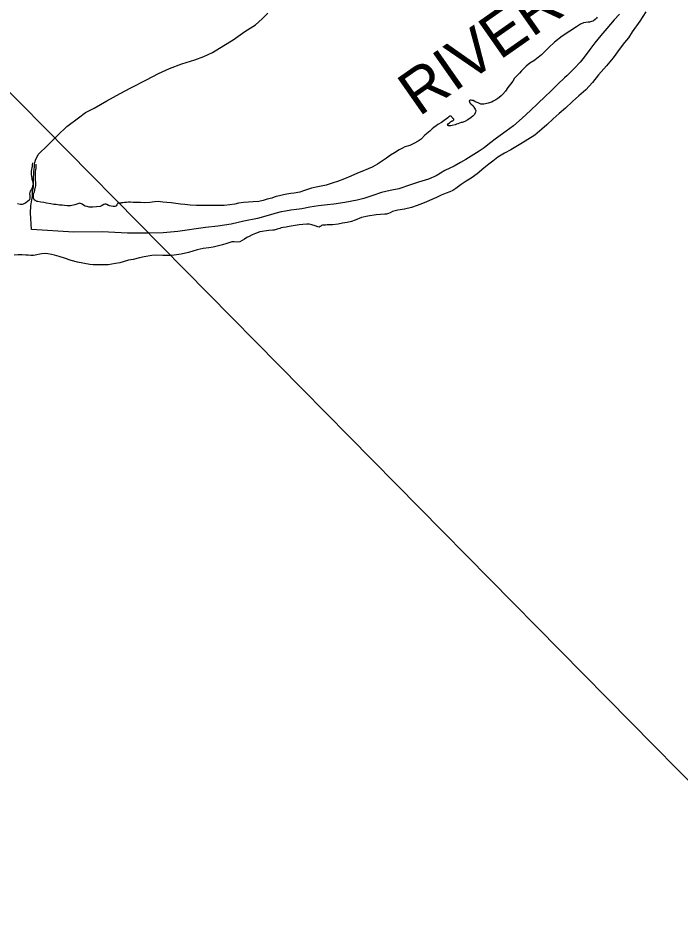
# Model space of a CAD drawing. Extents: x 31699 to 244310, y -8841 to 11474.
# Drawn here: x 101474 to 102106, y 1093 to 1951 of the extents above; entities that cross this region are included whole.
import ezdxf

# ---------------------------------------------------------------- set-up
doc = ezdxf.new("R2010")
doc.units = 0
for name, color, linetype in [('Level 48', 7, 'Continuous'), ('R_Draft', 7, 'Continuous'), ('R_Logo', 7, 'Continuous')]:
    doc.layers.add(name, color=color, linetype=linetype)

msp = doc.modelspace()

# ---------------------------------------------------------------- linework, layer by layer
at = {"layer": 'Level 48'}
msp.add_line((100000.09, 3366.76), (102655.5, 673.93), dxfattribs=at)
at = {"layer": 'R_Draft'}
for points in [[(102073.48, 1957.14), (102067.72, 1948.24)], [(102067.72, 1948.24), (102060.52, 1938.03), (102057, 1932.59), (102053.33, 1927.96), (102049.14, 1922.5), (102042.39, 1913.44), (102036, 1905.66), (102028.5, 1897.18), (102022.5, 1889.68), (102016.15, 1882.83), (102009.45, 1876.98), (102003.66, 1871.48), (101996.7, 1865.16), (101990.71, 1860.19), (101985.11, 1855.03), (101979, 1849.26), (101974.19, 1845.06), (101967.47, 1839.54), (101960.72, 1835.29), (101954.04, 1831.03), (101944.53, 1825.57), (101938.49, 1822.14), (101932.2, 1818.37), (101927.37, 1814.7), (101923.52, 1811.66), (101918.69, 1807.92), (101912.37, 1802.68), (101906.62, 1798.39), (101902.1, 1795.46), (101897.25, 1792.33), (101894.51, 1790.32), (101892.09, 1788.52), (101889.15, 1786.57), (101886.32, 1785.23), (101882.76, 1783.93), (101878.21, 1782.01), (101873.74, 1779.95), (101869.06, 1777.96), (101864.06, 1775.75), (101860.3, 1774.12), (101855.09, 1772.18), (101849.62, 1770.36), (101843.06, 1768.92), (101836.63, 1767.81), (101831.54, 1766.4), (101829.37, 1765.41), (101827.86, 1764.5), (101826.01, 1764.05), (101824.21, 1763.87), (101815.91, 1763.25), (101807.88, 1762.17), (101802.06, 1760.68), (101795.93, 1758.24), (101792.56, 1757.08), (101788.39, 1756.1), (101783.95, 1755.25), (101779.84, 1754.54), (101774.2, 1753.86), (101771.27, 1753.71), (101769.14, 1753.65), (101767.61, 1753.61), (101765.75, 1753.43), (101764.62, 1753.33), (101763.9, 1753.05), (101763.17, 1752.69), (101762.46, 1752.07), (101761.4, 1751.64), (101760.2, 1751.81), (101757.64, 1752.81), (101754.69, 1753.73), (101752.01, 1754.33), (101749.68, 1754.4), (101745.82, 1754.1), (101742.51, 1753.68), (101738.66, 1753.11), (101732.89, 1752.15), (101731.37, 1751.78), (101730.11, 1751.61), (101727.25, 1751.26), (101725.13, 1750.87), (101724.08, 1750.38), (101722.83, 1749.94), (101721.51, 1749.51), (101719.65, 1749.06), (101718.46, 1748.76), (101717.33, 1748.8)], [(102027.19, 1952.16), (102026.35, 1951.2), (102025.05, 1950.03), (102023.42, 1948.79), (102022.89, 1948.44), (102021.71, 1948.01), (102019.72, 1947.55), (102018.4, 1947.32), (102016.2, 1947.06), (102014.08, 1946.94), (102011.05, 1945.65), (102007.45, 1943.02), (102001.04, 1938.78), (101993.57, 1933.9), (101986.47, 1928.17), (101981, 1923.28), (101977.88, 1920.2), (101973.86, 1916.35), (101970.66, 1913.73), (101966.42, 1910.54), (101962.81, 1908.31), (101959.23, 1905.41), (101957.09, 1903.15), (101954.81, 1900.95), (101952.74, 1898.7), (101948.21, 1893.83), (101946.48, 1891.18), (101944.36, 1888.19), (101941.85, 1884.92), (101939.41, 1881.45), (101937.02, 1878.71), (101935.33, 1877), (101933.44, 1875.35), (101932.13, 1874.44), (101930.23, 1873.26), (101927.87, 1871.86), (101926.36, 1871.15), (101922.99, 1870.19), (101920.54, 1869.53), (101918.75, 1869.08), (101917.03, 1868.97), (101915.95, 1869.2), (101914.81, 1869.71), (101913.33, 1870.4), (101911.51, 1871.02), (101910.17, 1871.52), (101908.54, 1872.48), (101907.81, 1872.66), (101906.87, 1872.83), (101906.27, 1872.82), (101905.74, 1872.8)], [(101905.74, 1872.8), (101905.14, 1872.72), (101904.82, 1872.38), (101904.69, 1872.17), (101905.04, 1871.32), (101905.54, 1870.26), (101906.5, 1869.29), (101908.55, 1867.34), (101909.3, 1866.29), (101910.06, 1865.38), (101910.69, 1864.39), (101911.2, 1862.6), (101910.9, 1861.33), (101910.65, 1860.65), (101909.75, 1859.36), (101908.27, 1857.58), (101906.64, 1856.27), (101903.69, 1854.26), (101900.54, 1852.5), (101897.97, 1851.57), (101897.17, 1851.41), (101893.94, 1850.32), (101892.69, 1849.82), (101891.44, 1849.32), (101888.65, 1848.71), (101887.27, 1848.28), (101886.34, 1848.25), (101885.67, 1848.37), (101885.07, 1848.42), (101884.53, 1848.67), (101884.17, 1849.46), (101884.37, 1849.73), (101885.21, 1850.62), (101885.99, 1851.31), (101887.04, 1852.07), (101888.08, 1852.84), (101888.67, 1853.05), (101889.27, 1853.2), (101889.99, 1853.76), (101890.24, 1854.23), (101890.16, 1854.76), (101889.35, 1855.41), (101888.87, 1855.93), (101888.24, 1856.78), (101887.83, 1857.24), (101887.29, 1857.62), (101886.42, 1857.73), (101885.31, 1856.9), (101884.41, 1855.88), (101883.3, 1854.98), (101881.01, 1853.38), (101878.39, 1851.71), (101875.04, 1849.68), (101873.15, 1848.37), (101870.93, 1846.64), (101869.49, 1845.6), (101867.09, 1843.26), (101862.59, 1839.47), (101858.83, 1835.76), (101856.15, 1833.76), (101852.08, 1831.45), (101848.2, 1829.74), (101843.51, 1828.21), (101841.01, 1827.01), (101838.06, 1825.4), (101833.46, 1822.74), (101829.6, 1820.36), (101825.87, 1817.59), (101820.18, 1813.7), (101817.1, 1811.68), (101814.87, 1810.42), (101812.18, 1809.01), (101808.36, 1807.44), (101802.24, 1804.74), (101798.28, 1803.1), (101791.63, 1800.39), (101785.77, 1797.69), (101779.18, 1795.05), (101774.89, 1793.8), (101768.21, 1791.82), (101760.26, 1790.2), (101754.11, 1788.83), (101750.48, 1787.6), (101746.65, 1786.23), (101742.95, 1785.13), (101737.71, 1784.12), (101734.53, 1783.77), (101730.68, 1783.07), (101727.5, 1782.45), (101723.6, 1781.61), (101720.49, 1780.86), (101718.7, 1780.34), (101716.2, 1779.41)], [(101487.73, 1812.99), (101487.46, 1811.11), (101487.32, 1809.31), (101487.16, 1808.17), (101486.93, 1807.02), (101486.47, 1804.8), (101486.45, 1803.53), (101486.43, 1801.93), (101486.62, 1800.33), (101486.71, 1799.6), (101486.95, 1798.34), (101487.12, 1797.41), (101487.7, 1795.83), (101488.29, 1792.24), (101487.87, 1790.82), (101487.53, 1789.08), (101486.72, 1787.58), (101485.44, 1785.87), (101484.79, 1783.57), (101485.05, 1781.71), (101485.29, 1780.58), (101485.24, 1779.85), (101484.78, 1777.69), (101484.21, 1777.01), (101483.11, 1775.97), (101481.41, 1774.91), (101480.44, 1774.2), (101477.73, 1773.38), (101476.4, 1773.2), (101473.39, 1773.76)], [(101490.54, 1800.8), (101490.62, 1802.27), (101490.57, 1803.74), (101490.54, 1804.61), (101490.95, 1806.36), (101491.17, 1807.84), (101491.25, 1809.18), (101491.16, 1809.91), (101491.19, 1811.11), (101491.3, 1811.85)], [(101716.2, 1779.41), (101711.87, 1778.32), (101708.17, 1777.19), (101704.01, 1776.24), (101698.35, 1775.85), (101693.9, 1775.56), (101689.19, 1775.07), (101684.54, 1774.44), (101681.04, 1773.65), (101676.33, 1772.89), (101670.88, 1772.43), (101664.49, 1772.41), (101657.69, 1772.31), (101654.09, 1772.32), (101650.63, 1772.13), (101647.1, 1772.14), (101644.23, 1772.31), (101638.42, 1772.65), (101633.21, 1773.2), (101628.99, 1773.59), (101624.64, 1774.17), (101620.22, 1774.82), (101616.08, 1775.21), (101612.34, 1775.48), (101607.72, 1775.99), (101604.13, 1775.74), (101599.75, 1775.18), (101594.7, 1774.94), (101590.89, 1775.08), (101587.23, 1775.15), (101583.83, 1775.17), (101581.22, 1775.35), (101579.36, 1775.35), (101577.63, 1775.22), (101575.63, 1775.02), (101574.11, 1774.83), (101572.85, 1774.72), (101572.12, 1774.63), (101570.85, 1774.65), (101570.25, 1774.7), (101569.33, 1774.33), (101568.75, 1773.71), (101568.25, 1772.76), (101567.74, 1772.01), (101567.35, 1771.73), (101566.36, 1771.29), (101564.83, 1771.24), (101563.03, 1771.51), (101561.34, 1771.99), (101560.46, 1772.43), (101558.84, 1773.17), (101558.03, 1773.41), (101557.29, 1773.58), (101556.69, 1773.5), (101555.91, 1773.14), (101554.14, 1772.14), (101552.43, 1771.48), (101548.85, 1770.96), (101545.26, 1770.7), (101541.99, 1770.72), (101539.98, 1771.18), (101538.03, 1771.72), (101536.6, 1772.47), (101535.1, 1773.55), (101533.01, 1774.35), (101531.09, 1774.02), (101528.19, 1772.85), (101523.89, 1771.96), (101520.69, 1772.05), (101518.42, 1772.24), (101516.08, 1772.5), (101513.61, 1772.68), (101510.33, 1773.1), (101507.99, 1773.22), (101505.24, 1773.79), (101501.01, 1774.65), (101498.59, 1775.3), (101495.65, 1775.53), (101492.9, 1775.97), (101491.96, 1776.21), (101491.42, 1776.39), (101490.27, 1777.02), (101489.44, 1777.79), (101488.95, 1778.64), (101488.71, 1779.7), (101488.67, 1780.9), (101488.7, 1782.24), (101488.79, 1783.51), (101489.53, 1785.2), (101489.94, 1786.89), (101490.09, 1788.3), (101490.45, 1789.58), (101490.86, 1791.26), (101490.88, 1792.6), (101490.91, 1793.73), (101490.8, 1794.8), (101490.62, 1796.2), (101490.52, 1797.26), (101490.6, 1798.8), (101490.57, 1799.67), (101490.54, 1800.8)], [(101717.33, 1748.8), (101713.61, 1748.39), (101704.92, 1747.09), (101700.84, 1745.61), (101697.62, 1744.23), (101694.67, 1742.79), (101692.58, 1741.59), (101690.36, 1740.17), (101688.14, 1738.9), (101685.78, 1737.61), (101683.12, 1737.39), (101680.38, 1737.63), (101678.12, 1737.68), (101673.5, 1736.12), (101669.29, 1734.64), (101660.36, 1732.53), (101656.19, 1731.71), (101650.88, 1731.2), (101644.86, 1729.92), (101636.82, 1727.24), (101629.67, 1725.79), (101620.79, 1724.41), (101612.25, 1724.59), (101606.38, 1724.79), (101601.79, 1724.49), (101594.3, 1723.37), (101589.81, 1722.21), (101583.79, 1720.8), (101579.35, 1720.18), (101574.41, 1718.41), (101571.17, 1717.63), (101567.13, 1716.82), (101563.48, 1716.36), (101559.91, 1715.7), (101555.18, 1715.47), (101551.05, 1715.53), (101545.72, 1715.54), (101542.51, 1715.9), (101530.56, 1718.29), (101524.58, 1719.82), (101518.18, 1721.87), (101513.07, 1723.43), (101508.89, 1724.69), (101505.93, 1725.53), (101502.51, 1726.21), (101500.1, 1726.39), (101496.78, 1726.14), (101494.79, 1725.88), (101491.75, 1725.04), (101488.57, 1724.66), (101486.1, 1724.57), (101483.57, 1724.69), (101481.43, 1724.81), (101477.76, 1725.02), (101474.03, 1725.03), (101470.17, 1724.83)]]:
    msp.add_lwpolyline(points, dxfattribs=at)
at = {"layer": 'R_Logo'}
for points in [[(101717.13, 1763.95), (101702.63, 1759.83), (101689.59, 1757.25), (101677.55, 1754.43), (101664.76, 1752.38), (101652.93, 1751.37), (101626.48, 1747.45), (101612.46, 1746.17), (101599.94, 1745.87), (101578.61, 1746), (101554.18, 1747.23), (101527.27, 1746.83), (101486.74, 1749.38), (101485.73, 1765.3), (101486.24, 1772.07), (101487.18, 1777.78), (101487.68, 1780.87), (101487.72, 1783.54), (101487.78, 1785.68), (101488.29, 1788.23), (101488.75, 1790.45), (101488.72, 1791.52), (101488.79, 1793.39), (101488.71, 1795.66), (101488.74, 1796.8), (101488.79, 1799.14), (101488.96, 1802.08), (101489.15, 1804.49), (101489.26, 1806.9), (101489.53, 1808.85), (101489.72, 1811.06), (101489.75, 1812.13), (101489.92, 1813.2), (101490.63, 1815.7), (101492.99, 1821.06), (101502.35, 1829.93), (101511.83, 1839.34), (101520.61, 1847.79), (101531.52, 1856.18), (101538.42, 1861.03), (101546.48, 1865.25), (101558.64, 1872.21), (101571.32, 1879.33), (101581.67, 1884.76), (101596.54, 1892.42), (101608.07, 1898.23), (101618.43, 1903.27), (101630.21, 1907.75), (101642.94, 1911.59), (101651.3, 1914.69), (101659.51, 1918.31), (101670.54, 1924.97), (101679.35, 1930.62), (101690.55, 1938.35), (101700.6, 1944.84), (101707.14, 1950.48), (101712.44, 1956.16)], [(102048.43, 1955.06), (102043.44, 1949.52), (102036.26, 1941.52), (102030.64, 1934.83), (102024.7, 1927.59), (102020.01, 1921.39), (102014.67, 1913.9), (102010.86, 1909.33), (102005.36, 1903.44), (101998.48, 1896.58), (101995.88, 1894.11), (101989.5, 1888.33), (101982.75, 1881.61), (101977.43, 1876.32), (101970.55, 1869.66), (101963.33, 1862.93), (101955.53, 1855.71), (101947.26, 1848.34), (101940.14, 1843.15), (101930.93, 1836.49), (101924.33, 1831.44), (101919.11, 1827.36), (101914.47, 1824.17), (101906.87, 1819.29), (101901.56, 1816.08), (101896.44, 1813.2), (101890.47, 1809.91), (101881.59, 1805.6), (101873.19, 1800.7), (101865.96, 1797.37), (101856.44, 1794.64), (101848.65, 1792.03), (101837.56, 1788.13), (101829.48, 1786.51)], [(101829.48, 1786.51), (101820.94, 1784.68), (101811.9, 1781.63), (101804.17, 1779.09), (101797.69, 1777.32), (101786.16, 1775.21), (101775.48, 1773.58), (101769.37, 1772.82), (101760.94, 1771.93), (101752.52, 1770.7), (101745.03, 1769.23), (101739.99, 1768.3), (101734.42, 1767.68), (101729.24, 1766.87), (101725.2, 1766.23), (101719.05, 1764.53), (101717.13, 1763.95)]]:
    msp.add_lwpolyline(points, dxfattribs=at)

# ---------------------------------------------------------------- texts
at = {"layer": 'R_Draft'}
msp.add_text('RIVER', height=42.24, rotation=35, dxfattribs=at).set_placement((101856.83, 1856.71))

doc.saveas('drawing.dxf')
